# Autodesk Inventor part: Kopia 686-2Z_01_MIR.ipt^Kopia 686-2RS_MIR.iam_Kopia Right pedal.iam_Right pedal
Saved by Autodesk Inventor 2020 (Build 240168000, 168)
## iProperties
Created: 2017-10
Part Number: Kopia 686-2Z_01_MIR.ipt^Kopia 686-2RS_MIR.iam_Kopia Right pedal.iam_Right pedal
Material: Ogólny
Document SubType Name: Modeling
Designer: Tomasz
Density: 1 g/cm^3
Appearance: Domyślna
Sending System: SolidWorks 2017
Last Author: Tomasz
Last Saved: 2017-10-01
Author: Tomasz
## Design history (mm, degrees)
